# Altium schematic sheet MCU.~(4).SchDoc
size A3; SheetNumber: 1; SheetTotal: 2
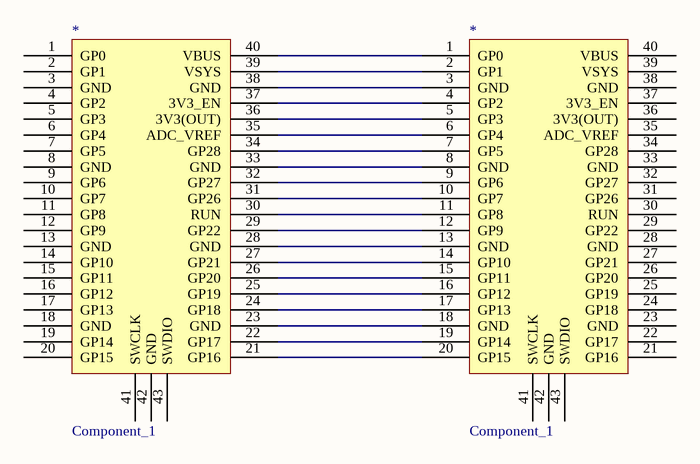
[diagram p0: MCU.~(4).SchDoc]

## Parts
(Parts that share a designator on the sheet are numbered #1, #2 ... from top to bottom, then left to right.)
*#1  Component_1  [PCBComponent_1]
*#2  Component_1  [PCBComponent_1]

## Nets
Net*#1_21: *#1.21(GP16) *#2.20(GP15)
Net*#1_22: *#1.22(GP17) *#2.19(GP14)
Net*#1_23: *#1.23(GND) *#2.18(GND)
Net*#1_24: *#1.24(GP18) *#2.17(GP13)
Net*#1_25: *#1.25(GP19) *#2.16(GP12)
Net*#1_26: *#1.26(GP20) *#2.15(GP11)
Net*#1_27: *#1.27(GP21) *#2.14(GP10)
Net*#1_28: *#1.28(GND) *#2.13(GND)
Net*#1_29: *#1.29(GP22) *#2.12(GP9)
Net*#1_30: *#1.30(RUN) *#2.11(GP8)
Net*#1_31: *#1.31(GP26) *#2.10(GP7)
Net*#1_32: *#1.32(GP27) *#2.9(GP6)
Net*#1_33: *#1.33(GND) *#2.8(GND)
Net*#1_34: *#1.34(GP28) *#2.7(GP5)
Net*#1_35: *#1.35(ADC_VREF) *#2.6(GP4)
Net*#1_36: *#1.36(3V3(OUT)) *#2.5(GP3)
Net*#1_37: *#1.37(3V3_EN) *#2.4(GP2)
Net*#1_38: *#1.38(GND) *#2.3(GND)
Net*#1_39: *#1.39(VSYS) *#2.2(GP1)
Net*#1_40: *#1.40(VBUS) *#2.1(GP0)

Not connected (* = marked no-connect by the designer): *#1 1(GP0) 2(GP1) 3(GND) 4(GP2) 5(GP3) 6(GP4) 7(GP5) 8(GND) 9(GP6) 10(GP7) 11(GP8) 12(GP9) 13(GND) 14(GP10) 15(GP11) 16(GP12) 17(GP13) 18(GND) 19(GP14) 20(GP15) 41(SWCLK) 42(GND) 43(SWDIO); *#2 21(GP16) 22(GP17) 23(GND) 24(GP18) 25(GP19) 26(GP20) 27(GP21) 28(GND) 29(GP22) 30(RUN) 31(GP26) 32(GP27) 33(GND) 34(GP28) 35(ADC_VREF) 36(3V3(OUT)) 37(3V3_EN) 38(GND) 39(VSYS) 40(VBUS) 41(SWCLK) 42(GND) 43(SWDIO)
